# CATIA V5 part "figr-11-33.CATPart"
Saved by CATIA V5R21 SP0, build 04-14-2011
Part number: Part1
Bounding box of the stored display mesh (mm): x -120 to 40, y -443 to 443, z -443 to 443
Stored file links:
  D:\CATIA V5R21 E-RESOURCES\CATIA-V5R21\catia-v5r21-prt\c11-catia-v5r21-prt\c11-catia-v5r21-figr-11-33.CATPart
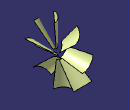
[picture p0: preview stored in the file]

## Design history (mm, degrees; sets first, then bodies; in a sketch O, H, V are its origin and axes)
Set1
  Plane1: type Offset, RefPlane xy-plane, Offset 443
  Sketch1 on Plane1, origin (0, 0, 443), H (1, 0, 0), V (0, 1, 0)
    arc A1 centre (51.3551, -160.9813) radius 171.358 from (40, 10) to (-120, -160) ccw
  Loft1: Sections (Sketch3; Sketch1)
  Sketch2 on zx-plane, origin (0, 0, 0), H (-1, 0, 0), V (0, 0, 1)
    line L1 (-270, 0) -> (280, 0)
    point P1 (-270, 0)
    coincidence: P1 H
    horizontal: L1 H
  Rotate1: ToTransfor Loft1, Axis Sketch2, Angle 45
  Rotate2: ToTransfor Loft1, Axis Sketch2, Angle 90 {= Rotate1.Angle * 2}
  Rotate3: ToTransfor Loft1, Axis Sketch2, Angle 135 {= Rotate1.Angle * 3}
  Rotate4: ToTransfor Loft1, Axis Sketch2, Angle 180 {= Rotate1.Angle * 4}
  Rotate5: ToTransfor Loft1, Axis Sketch2, Angle 225 {= Rotate1.Angle * 5}
  Rotate6: ToTransfor Loft1, Axis Sketch2, Angle 270 {= Rotate1.Angle * 6}
  Rotate7: ToTransfor Loft1, Axis Sketch2, Angle 315 {= Rotate1.Angle * 7}
  Rotate8: ToTransfor Loft1, Axis Sketch2, Angle 360 {= Rotate1.Angle * 8}
  Rotate9: ToTransfor Loft1, Axis Sketch2, Angle 405 {= Rotate1.Angle * 9}
Body1 (main body)
  Sketch3 on Plane2, origin (0, 0, 67), H (1, 0, 0), V (0, 1, 0)
    point P1 (-100, 0)
    arc A1 centre (50, -150) radius 158.1139 from (0, 0) to (-100, -100) ccw
Set2
  Plane2: type Offset, RefPlane xy-plane, Offset 67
